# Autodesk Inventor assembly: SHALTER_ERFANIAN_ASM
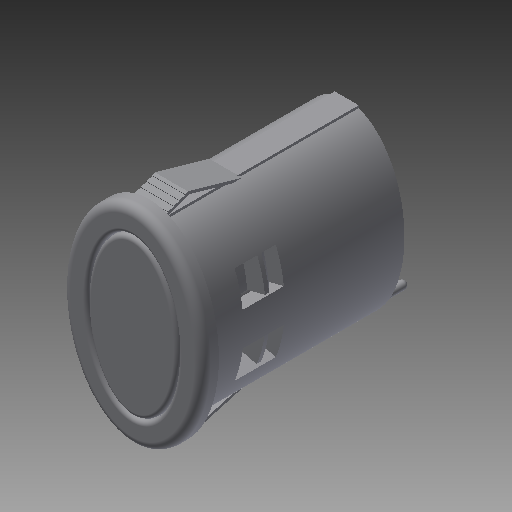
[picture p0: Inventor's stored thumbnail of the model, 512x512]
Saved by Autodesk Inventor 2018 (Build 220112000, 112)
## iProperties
Created: 2019-01
Part Number: SHALTER_ERFANIAN_ASM
Material: Generisch
Document SubType Name: Assembly
Designer: zand
Author: zand
Revision Number: 7LAST_VERSION
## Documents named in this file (3)
- W:\KAFFEEMASCHINE\Creo5-STEP-Inventor\STEP\SHALTER_ERFANIAN_ASM.iam
- W:\KAFFEEMASCHINE\Creo5-STEP-Inventor\STEP\SCHLATERGEHAEUSE_ERFANIAN.ipt
- W:\KAFFEEMASCHINE\Creo5-STEP-Inventor\STEP\LICHT_ROT_ERFANIAN.ipt
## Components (2 placed, 2 different names)
1. Schaltergehaeuse
2. Licht_rot
